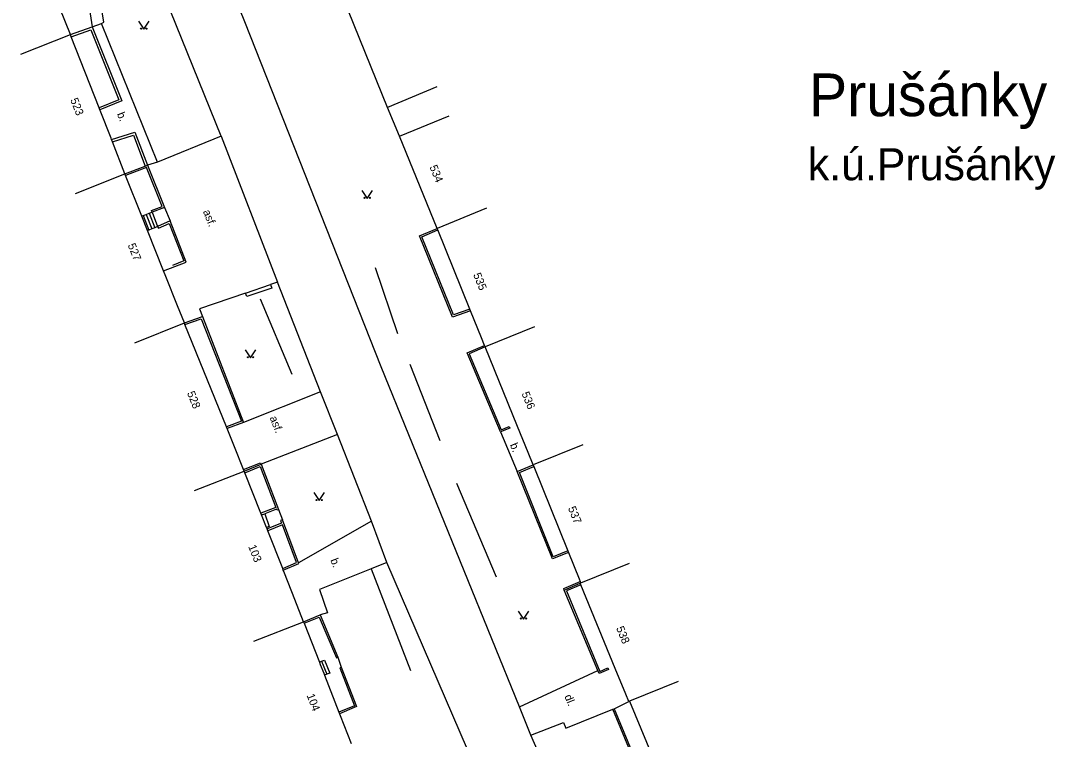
# Model space of a CAD drawing. Extents: x -577457 to -568404, y -1208466 to -1201387.
# Drawn here: x -575140.8 to -575043.9, y -1204885.6 to -1204818.3 of the extents above; entities that cross this region are included whole.
import ezdxf

# ---------------------------------------------------------------- set-up
doc = ezdxf.new("R2010")
doc.units = 0
for name, color, linetype in [('BUDOVY_MĚŘ', 7, 'Continuous'), ('NÁZEV_K_Ú', 7, 'Continuous'), ('NÁZVY_SÍDEL_JEDNOTKY', 7, 'Continuous'), ('POMOC_POPIS', 7, 'Continuous'), ('ROZHRANÍ_PLOCH', 7, 'Continuous'), ('ZN_DOPLŇKOVÉ', 7, 'Continuous'), ('ZN_KULTUR', 7, 'Continuous'), ('Č_POPIS_ORIENT', 7, 'Continuous')]:
    doc.layers.add(name, color=color, linetype=linetype)

msp = doc.modelspace()

# ---------------------------------------------------------------- linework, layer by layer
at = {"layer": 'BUDOVY_MĚŘ'}
for points in [[(-575136.14, -1204819.57), (-575138.58, -1204813.44)], [(-575140.79, -1204821.39), (-575136.14, -1204819.57)], [(-575136.06, -1204819.77), (-575136.14, -1204819.57)], [(-575133.45, -1204826.43), (-575136.06, -1204819.77)], [(-575133.37, -1204826.63), (-575133.45, -1204826.43)], [(-575133.35, -1204826.69), (-575133.37, -1204826.63)], [(-575105.3, -1204829.07), (-575100.67, -1204827.19)], [(-575132.28, -1204829.4), (-575132.33, -1204829.27)], [(-575132.2, -1204829.6), (-575132.28, -1204829.4)], [(-575131.02, -1204832.61), (-575132.2, -1204829.6)], [(-575101.79, -1204837.72), (-575105.3, -1204829.07)], [(-575135.66, -1204834.46), (-575131.02, -1204832.61)], [(-575130.96, -1204832.76), (-575131.02, -1204832.61)], [(-575129.44, -1204836.58), (-575130.96, -1204832.76)], [(-575097.16, -1204835.84), (-575101.79, -1204837.72)], [(-575127.4, -1204841.7), (-575128.9, -1204837.92)], [(-575101.73, -1204837.87), (-575101.79, -1204837.72)], [(-575098.72, -1204845.3), (-575101.73, -1204837.87)], [(-575127.19, -1204842.22), (-575127.4, -1204841.7)], [(-575125.46, -1204846.57), (-575126.09, -1204844.99)], [(-575098.66, -1204845.44), (-575098.72, -1204845.3)], [(-575130.1, -1204848.44), (-575125.46, -1204846.57)], [(-575125.4, -1204846.72), (-575125.46, -1204846.57)], [(-575121.52, -1204856.32), (-575125.4, -1204846.72)], [(-575092.65, -1204846.95), (-575097.29, -1204848.83)], [(-575097.35, -1204848.69), (-575097.63, -1204847.99)], [(-575097.29, -1204848.83), (-575097.35, -1204848.69)], [(-575094.26, -1204856.28), (-575097.29, -1204848.83)], [(-575121.46, -1204856.47), (-575121.52, -1204856.32)], [(-575120.71, -1204858.35), (-575121.46, -1204856.47)], [(-575092.79, -1204859.89), (-575093.26, -1204858.74)], [(-575088.15, -1204858.02), (-575092.79, -1204859.89)], [(-575124.5, -1204862.3), (-575119.85, -1204860.47)], [(-575119.91, -1204860.33), (-575119.98, -1204860.16)], [(-575119.85, -1204860.47), (-575119.91, -1204860.33)], [(-575119.78, -1204860.64), (-575119.85, -1204860.47)], [(-575118.29, -1204864.41), (-575119.78, -1204860.64)], [(-575092.79, -1204859.89), (-575092.73, -1204860.04)], [(-575092.73, -1204860.04), (-575089.53, -1204867.94)], [(-575118.23, -1204864.57), (-575118.29, -1204864.41)], [(-575118.18, -1204864.71), (-575118.23, -1204864.57)], [(-575117.76, -1204865.76), (-575117.83, -1204865.59)], [(-575117.71, -1204865.89), (-575117.76, -1204865.76)], [(-575117.65, -1204866.05), (-575117.71, -1204865.89)], [(-575116.25, -1204869.6), (-575117.65, -1204866.05)], [(-575089.53, -1204867.94), (-575089.47, -1204868.09)], [(-575088.31, -1204870.95), (-575083.75, -1204869.08)], [(-575116.19, -1204869.76), (-575116.25, -1204869.6)], [(-575116.09, -1204870.02), (-575116.19, -1204869.76)], [(-575088.47, -1204870.57), (-575088.37, -1204870.81)], [(-575088.38, -1204870.98), (-575088.31, -1204870.95)], [(-575088.32, -1204871.13), (-575088.38, -1204870.98)], [(-575088.37, -1204870.81), (-575088.31, -1204870.95)], [(-575085.11, -1204878.96), (-575088.32, -1204871.13)], [(-575114.29, -1204874.58), (-575115.11, -1204872.49)], [(-575118.94, -1204876.4), (-575114.29, -1204874.58)], [(-575114.29, -1204874.58), (-575114.23, -1204874.72)], [(-575114.23, -1204874.72), (-575112.81, -1204878.36)], [(-575112.81, -1204878.36), (-575112.73, -1204878.58)], [(-575112.41, -1204879.41), (-575112.34, -1204879.58)], [(-575112.34, -1204879.58), (-575110.98, -1204883.07)], [(-575079.2, -1204880.17), (-575083.76, -1204882.04)], [(-575083.83, -1204882.07), (-575084.12, -1204881.37)], [(-575083.76, -1204882.04), (-575083.83, -1204882.07)], [(-575083.76, -1204882.04), (-575080.59, -1204889.71)], [(-575110.98, -1204883.07), (-575110.93, -1204883.21)], [(-575110.93, -1204883.21), (-575110.87, -1204883.37)]]:
    msp.add_lwpolyline(points, dxfattribs=at)
at = {"layer": 'ROZHRANÍ_PLOCH'}
for points in [[(-575094.08, -1204882.55), (-575107.04, -1204850.7), (-575119.81, -1204818.36), (-575128.63, -1204796.54), (-575125.63, -1204795.35), (-575127.01, -1204791.42), (-575129.27, -1204792.23), (-575137.73, -1204771.17)], [(-575133.21, -1204818.53), (-575132.99, -1204818.4), (-575133.64, -1204814.58), (-575136.48, -1204807.67), (-575131.5, -1204805.6)], [(-575122.01, -1204829.07), (-575131.5, -1204805.6)], [(-575135.75, -1204812.3), (-575134.69, -1204814.94), (-575134.09, -1204818.84)], [(-575134.09, -1204818.84), (-575133.21, -1204818.53)], [(-575127.97, -1204831.51), (-575133.21, -1204818.53)], [(-575122.01, -1204829.07), (-575127.97, -1204831.51)], [(-575122.01, -1204829.07), (-575116.73, -1204842.77)], [(-575127.97, -1204831.51), (-575128.92, -1204831.8)], [(-575129.44, -1204836.58), (-575129.31, -1204836.53)], [(-575129.31, -1204836.53), (-575129.03, -1204836.42)], [(-575129.31, -1204836.53), (-575128.8, -1204837.88)], [(-575129.03, -1204836.42), (-575128.76, -1204836.31)], [(-575129.03, -1204836.42), (-575128.52, -1204837.77)], [(-575128.76, -1204836.31), (-575128.48, -1204836.2)], [(-575128.76, -1204836.31), (-575128.24, -1204837.66)], [(-575128.48, -1204836.2), (-575127.96, -1204837.55)], [(-575127.31, -1204835.76), (-575126.8, -1204837.03)], [(-575127.96, -1204837.55), (-575128.24, -1204837.66)], [(-575128.8, -1204837.88), (-575128.9, -1204837.92)], [(-575128.52, -1204837.77), (-575128.8, -1204837.88)], [(-575128.24, -1204837.66), (-575128.52, -1204837.77)], [(-575116.73, -1204842.77), (-575117.38, -1204842.99)], [(-575112.7, -1204853.04), (-575116.73, -1204842.77)], [(-575119.72, -1204843.78), (-575124.05, -1204845.26), (-575123.77, -1204845.99)], [(-575112.7, -1204853.04), (-575119.92, -1204855.9)], [(-575111.13, -1204857.04), (-575112.7, -1204853.04)], [(-575095.86, -1204856.8), (-575094.29, -1204860.5)], [(-575111.13, -1204857.04), (-575118.27, -1204859.82)], [(-575107.93, -1204865.17), (-575111.13, -1204857.04)], [(-575118.23, -1204864.57), (-575117.93, -1204864.46)], [(-575117.93, -1204864.46), (-575117.53, -1204865.66), (-575117.76, -1204865.76)], [(-575116.64, -1204864.06), (-575116.27, -1204865.03)], [(-575107.93, -1204865.17), (-575114.76, -1204869.06)], [(-575106.49, -1204869.02), (-575107.93, -1204865.17)], [(-575106.49, -1204869.02), (-575107.96, -1204869.61)], [(-575080.87, -1204923.74), (-575081.57, -1204922.81), (-575082.98, -1204920.78), (-575084.32, -1204918.72), (-575085.6, -1204916.61), (-575086.64, -1204914.71), (-575087.62, -1204912.76), (-575088.52, -1204910.79), (-575089.34, -1204908.78), (-575089.4, -1204908.63), (-575106.49, -1204869.02)], [(-575107.96, -1204869.61), (-575112.81, -1204871.55), (-575112.04, -1204873.76), (-575112.75, -1204873.95)], [(-575112.61, -1204878.28), (-575112.33, -1204878.17), (-575111.84, -1204879.39), (-575112.12, -1204879.5)], [(-575112.81, -1204878.36), (-575112.61, -1204878.28)], [(-575112.61, -1204878.28), (-575112.12, -1204879.5)], [(-575094.08, -1204882.55), (-575086.74, -1204879.15)], [(-575112.12, -1204879.5), (-575112.34, -1204879.58)], [(-575085.21, -1204882.74), (-575083.83, -1204882.07)], [(-575093, -1204885.22), (-575094.08, -1204882.55)], [(-575093, -1204885.22), (-575089.95, -1204884.02), (-575089.74, -1204884.56), (-575085.34, -1204882.79)], [(-575089.79, -1204892.52), (-575093, -1204885.22)]]:
    msp.add_lwpolyline(points, dxfattribs=at)
at = {"layer": 'ZN_DOPLŇKOVÉ'}
for points in [[(-575106.42, -1204826.4), (-575110.6, -1204816.03)], [(-575136.14, -1204819.57), (-575134.09, -1204818.84)], [(-575136.06, -1204819.77), (-575134.22, -1204819.11), (-575131.61, -1204825.67), (-575133.45, -1204826.43)], [(-575134.09, -1204818.84), (-575131.32, -1204825.78), (-575133.37, -1204826.63)], [(-575101.81, -1204824.47), (-575106.42, -1204826.4)], [(-575132.33, -1204829.27), (-575133.35, -1204826.69)], [(-575105.3, -1204829.07), (-575106.42, -1204826.4)], [(-575132.28, -1204829.4), (-575130.1, -1204828.72), (-575128.92, -1204831.8)], [(-575132.2, -1204829.6), (-575130.23, -1204828.99), (-575129.13, -1204831.88)], [(-575131.02, -1204832.61), (-575129.13, -1204831.88)], [(-575128.48, -1204836.2), (-575128.54, -1204836.04), (-575127.53, -1204835.66), (-575129.02, -1204832.02), (-575130.96, -1204832.76)], [(-575129.13, -1204831.88), (-575128.92, -1204831.8)], [(-575128.92, -1204831.8), (-575127.31, -1204835.76)], [(-575128.9, -1204837.92), (-575129.44, -1204836.58)], [(-575127.31, -1204835.76), (-575128.48, -1204836.2)], [(-575126.8, -1204837.03), (-575127.96, -1204837.55)], [(-575127.96, -1204837.55), (-575127.89, -1204837.7), (-575126.89, -1204837.26), (-575125.52, -1204840.78), (-575126.57, -1204841.19)], [(-575127.4, -1204841.7), (-575125.3, -1204840.88), (-575126.8, -1204837.03)], [(-575098.66, -1204845.44), (-575100.33, -1204846.03), (-575103.43, -1204838.43), (-575101.79, -1204837.72)], [(-575098.72, -1204845.3), (-575100.24, -1204845.83), (-575103.22, -1204838.51), (-575101.73, -1204837.87)], [(-575105.45, -1204847.59), (-575107.56, -1204841.43)], [(-575126.09, -1204844.99), (-575127.19, -1204842.22)], [(-575119.72, -1204843.78), (-575117.38, -1204842.99)], [(-575117.26, -1204843.34), (-575119.6, -1204844.12), (-575119.72, -1204843.78)], [(-575117.38, -1204842.99), (-575117.26, -1204843.34)], [(-575118.36, -1204844.32), (-575115.38, -1204851.4)], [(-575125.46, -1204846.57), (-575123.77, -1204845.99)], [(-575125.4, -1204846.72), (-575123.87, -1204846.19), (-575120.12, -1204855.8), (-575121.52, -1204856.32)], [(-575123.77, -1204845.99), (-575119.92, -1204855.9)], [(-575097.63, -1204847.99), (-575098.66, -1204845.44)], [(-575095.86, -1204856.8), (-575098.98, -1204849.4), (-575097.35, -1204848.69)], [(-575097.29, -1204848.83), (-575098.78, -1204849.48), (-575095.78, -1204856.6), (-575095.02, -1204856.3), (-575094.96, -1204856.43), (-575095.86, -1204856.8)], [(-575101.49, -1204857.64), (-575104.31, -1204850.48)], [(-575119.92, -1204855.9), (-575121.46, -1204856.47)], [(-575093.26, -1204858.74), (-575094.26, -1204856.28)], [(-575119.98, -1204860.16), (-575120.71, -1204858.35)], [(-575119.91, -1204860.33), (-575118.33, -1204859.68), (-575118.27, -1204859.82)], [(-575119.85, -1204860.47), (-575118.27, -1204859.82)], [(-575118.27, -1204859.82), (-575116.64, -1204864.06)], [(-575119.78, -1204860.64), (-575118.37, -1204860.05), (-575116.9, -1204863.88), (-575118.29, -1204864.41)], [(-575094.29, -1204860.5), (-575092.79, -1204859.89)], [(-575089.47, -1204868.09), (-575090.99, -1204868.7), (-575094.29, -1204860.5)], [(-575089.53, -1204867.94), (-575090.9, -1204868.49), (-575094.08, -1204860.59), (-575092.73, -1204860.04)], [(-575096.23, -1204870.4), (-575099.95, -1204861.64)], [(-575116.64, -1204864.06), (-575116.81, -1204864.12), (-575116.84, -1204864.05), (-575117.93, -1204864.46)], [(-575117.83, -1204865.59), (-575118.18, -1204864.71)], [(-575116.27, -1204865.03), (-575116.44, -1204865.1), (-575116.35, -1204865.34), (-575117.71, -1204865.89)], [(-575116.25, -1204869.6), (-575114.96, -1204869.04), (-575116.28, -1204865.51), (-575117.65, -1204866.05)], [(-575114.76, -1204869.06), (-575116.27, -1204865.03)], [(-575089.47, -1204868.09), (-575088.47, -1204870.57)], [(-575116.19, -1204869.76), (-575114.73, -1204869.14), (-575114.76, -1204869.06)], [(-575115.11, -1204872.49), (-575116.09, -1204870.02)], [(-575107.96, -1204869.61), (-575104.27, -1204879.14)], [(-575089.87, -1204871.61), (-575089.93, -1204871.47), (-575088.37, -1204870.81)], [(-575089.87, -1204871.61), (-575088.38, -1204870.98)], [(-575088.32, -1204871.13), (-575089.66, -1204871.7), (-575086.53, -1204879.23), (-575085.8, -1204878.91), (-575085.73, -1204879.06), (-575086.62, -1204879.44), (-575086.74, -1204879.15)], [(-575086.74, -1204879.15), (-575089.87, -1204871.61)], [(-575114.29, -1204874.58), (-575112.75, -1204873.95)], [(-575114.23, -1204874.72), (-575112.83, -1204874.14), (-575111.22, -1204877.96), (-575111.08, -1204877.9)], [(-575112.75, -1204873.95), (-575111.08, -1204877.9)], [(-575111.08, -1204877.9), (-575110.76, -1204878.85)], [(-575112.73, -1204878.58), (-575112.41, -1204879.41)], [(-575110.76, -1204878.85), (-575110.9, -1204878.91), (-575109.53, -1204882.45), (-575110.98, -1204883.07)], [(-575110.76, -1204878.85), (-575109.34, -1204882.53), (-575110.93, -1204883.21)], [(-575084.12, -1204881.37), (-575085.11, -1204878.96)], [(-575085.34, -1204882.79), (-575085.21, -1204882.74)], [(-575082.32, -1204890.02), (-575085.34, -1204882.79)], [(-575085.21, -1204882.74), (-575082.25, -1204889.84), (-575081.37, -1204889.46), (-575081.31, -1204889.58)], [(-575110.87, -1204883.37), (-575109.85, -1204885.98)]]:
    msp.add_lwpolyline(points, dxfattribs=at)
at = {"layer": 'ZN_KULTUR'}
for points in [[(-575129.76, -1204818.31), (-575129.26, -1204819.06), (-575128.76, -1204818.31)], [(-575108.84, -1204834.16), (-575108.34, -1204834.91), (-575107.84, -1204834.16)], [(-575119.76, -1204849.1), (-575119.26, -1204849.85), (-575118.76, -1204849.1)], [(-575113.34, -1204862.48), (-575112.84, -1204863.23), (-575112.34, -1204862.48)], [(-575094.19, -1204873.58), (-575093.69, -1204874.33), (-575093.19, -1204873.58)]]:
    msp.add_lwpolyline(points, dxfattribs=at)
for centre in [(-575129.51, -1204819.01), (-575129.01, -1204819.01), (-575108.59, -1204834.86), (-575108.09, -1204834.86), (-575119.51, -1204849.8), (-575119.01, -1204849.8), (-575113.09, -1204863.18), (-575112.59, -1204863.18), (-575093.94, -1204874.28), (-575093.44, -1204874.28)]:
    msp.add_circle(centre, 0.05, dxfattribs=at)

# ---------------------------------------------------------------- texts
at = {"layer": 'NÁZEV_K_Ú'}
msp.add_text('k.ú.Prušánky', height=3, dxfattribs=at).set_placement((-575067.06, -1204833.21))
at = {"layer": 'NÁZVY_SÍDEL_JEDNOTKY'}
msp.add_text('Prušánky', height=4, dxfattribs=at).set_placement((-575066.94, -1204827.21))
at = {"layer": 'POMOC_POPIS'}
for s, rotation, p in [('b.', 291.69001, (-575131.79, -1204827)), ('asf.', 291.69001, (-575123.73, -1204836.14)), ('asf.', 291.52001, (-575117.48, -1204855.47)), ('b.', 292.12998, (-575094.98, -1204858)), ('b.', 291.52001, (-575111.8, -1204868.8)), ('dl.', 292.31997, (-575089.88, -1204881.57))]:
    msp.add_text(s, height=0.75, rotation=rotation, dxfattribs=at).set_placement(p)
at = {"layer": 'Č_POPIS_ORIENT'}
for s, rotation, p in [('523', 291.44002, (-575136.16, -1204825.67)), ('534', 292.08999, (-575102.51, -1204831.96)), ('527', 291.69001, (-575130.78, -1204839.29)), ('535', 292.08002, (-575098.42, -1204842.06)), ('528', 291.99001, (-575125.23, -1204853.15)), ('536', 292.12998, (-575093.89, -1204853.2)), ('537', 292.01997, (-575089.54, -1204863.94)), ('103', 291.52001, (-575119.49, -1204867.53)), ('538', 292.31997, (-575085.03, -1204875.18)), ('104', 291.27003, (-575114.02, -1204881.48))]:
    msp.add_text(s, height=0.75, rotation=rotation, dxfattribs=at).set_placement(p)

doc.saveas('drawing.dxf')
